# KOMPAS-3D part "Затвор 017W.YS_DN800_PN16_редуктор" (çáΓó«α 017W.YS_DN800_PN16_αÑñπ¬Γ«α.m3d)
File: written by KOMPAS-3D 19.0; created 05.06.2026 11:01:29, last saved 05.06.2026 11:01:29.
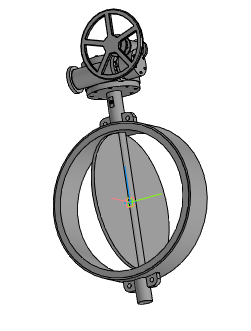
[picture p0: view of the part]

Document properties: Автор: Энергия; Полное имя файла: ..\..\..\3d для проектировщиков\x.x Тип 017W.Y(S) Затвор дисковый поворотный межфланцевый\Затвор 017W.Y(S)_DN50-DN1200_редуктор\Затвор 017W.YS_DN800_PN16_редуктор.a3d

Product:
- Part/product: Затвор 017W.YS_DN800_PN16_редуктор
    Масса: 469.715

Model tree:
1. Операция без истории:1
